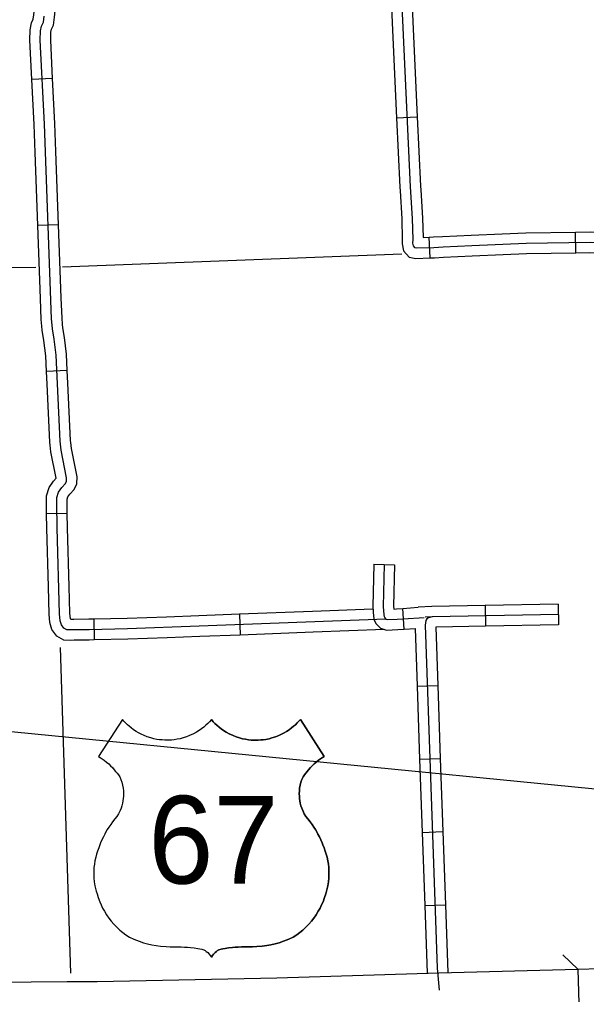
# Model space of a CAD drawing. Extents: x 1164457 to 1439835, y 1590918 to 1773502.
# Drawn here: x 1271432 to 1275531, y 1634109 to 1641151 of the extents above; entities that cross this region are included whole.
import ezdxf

# ---------------------------------------------------------------- set-up
doc = ezdxf.new("R2010")
doc.units = 0
for name, color, linetype in [('Level 15', 7, 'Continuous'), ('Level 22', 7, 'Continuous'), ('Level 32', 7, 'Continuous'), ('Level 37', 7, 'Continuous'), ('Level 45', 7, 'Continuous'), ('Level 49', 7, 'Continuous'), ('Level 5', 7, 'Continuous'), ('R_Draft', 7, 'Continuous')]:
    doc.layers.add(name, color=color, linetype=linetype)

msp = doc.modelspace()

# ---------------------------------------------------------------- linework, layer by layer
at = {"layer": 'Level 15'}
for points in [[(1264028.8, 1633877.9), (1264019.5, 1634127.7), (1266582.9, 1634223.2), (1269170.9, 1634189.2), (1269688.7, 1634190.8), (1270471.2, 1634190.8), (1271775.7, 1634202.7), (1271994.3, 1634202.4), (1273292.2, 1634228.7), (1274462.5, 1634266.1), (1275467.6, 1634293)], [(1275467.6, 1634293), (1275474.3, 1634043.1), (1274469.8, 1634016.2), (1273298.7, 1633978.7), (1271996.7, 1633952.4), (1271776.7, 1633952.7), (1270472.3, 1633940.8), (1269689.1, 1633940.8), (1269169.6, 1633939.2), (1266585.9, 1633973.1), (1264028.8, 1633877.9)], [(1275467.6, 1634293), (1275952.7, 1634306.1)]]:
    msp.add_lwpolyline(points, dxfattribs=at)
at = {"layer": 'Level 22'}
for points in [[(1272818.6, 1636094.4), (1272805.5, 1636079.6), (1272792.9, 1636066.7), (1272778.6, 1636053.3), (1272763.2, 1636040.1), (1272748.3, 1636028.5), (1272730.2, 1636015.9), (1272710.9, 1636003.8), (1272688.8, 1635991.7), (1272660.8, 1635978.7), (1272639.3, 1635970.3), (1272615, 1635962.5), (1272592.8, 1635956.7), (1272572.3, 1635952.5), (1272550.7, 1635949.1), (1272530.8, 1635947.1), (1272503.6, 1635945.8), (1272481.5, 1635946.1), (1272462.2, 1635947.3), (1272443.9, 1635949.2), (1272425.4, 1635952), (1272402, 1635956.7), (1272380.4, 1635962.4), (1272354.1, 1635971), (1272331.8, 1635979.7), (1272311.6, 1635989), (1272293, 1635998.7), (1272275.9, 1636008.8), (1272256.7, 1636021.4), (1272239.2, 1636034.3), (1272224.1, 1636046.6), (1272211.3, 1636057.9), (1272198.3, 1636070.5), (1272185.5, 1636084), (1272175.2, 1636095.8), (1272002.1, 1635828.1), (1272014.5, 1635820.8), (1272029.2, 1635811.1), (1272043.2, 1635801.2), (1272061.7, 1635786.8), (1272076.6, 1635774), (1272089.8, 1635761.7), (1272103.1, 1635748), (1272116.9, 1635732.8), (1272126.7, 1635720.9), (1272136.5, 1635708.4), (1272146.3, 1635694.6), (1272155.9, 1635680.1), (1272164.7, 1635663.1), (1272171.5, 1635642.3), (1272176.6, 1635621.6), (1272180.4, 1635599.5), (1272182.5, 1635579), (1272183.2, 1635559.1), (1272182.7, 1635540.6), (1272181.5, 1635525.7), (1272179, 1635507.5), (1272175.6, 1635490.3), (1272170.8, 1635471.8), (1272165.6, 1635455.5), (1272158.5, 1635437.2), (1272147.2, 1635413.6), (1272135.7, 1635395.1), (1272121.7, 1635378.4), (1272104.8, 1635356.6), (1272091.1, 1635337.6), (1272078.2, 1635318.5), (1272066.4, 1635299.8), (1272056.6, 1635283), (1272047.8, 1635267.3), (1272038.1, 1635248.6), (1272027.6, 1635226.8), (1272018.2, 1635205.4), (1272011.8, 1635189.5), (1272004.1, 1635169.2), (1271995.7, 1635144.2), (1271989, 1635123.5), (1271982.7, 1635100.9), (1271976.9, 1635074.6), (1271973, 1635051.2), (1271970.2, 1635026.8), (1271968.6, 1635000.2), (1271968.5, 1634975.2), (1271969.7, 1634950.7), (1271972.6, 1634922), (1271977.1, 1634894.8), (1271981.6, 1634874.2), (1271986.3, 1634856.1), (1271992.2, 1634835.7), (1272000.1, 1634810.3), (1272011.6, 1634779.5), (1272021.4, 1634756.8), (1272032.8, 1634733.4), (1272045.4, 1634710.5), (1272061.7, 1634684.2), (1272078.5, 1634660.1), (1272094.8, 1634639.1), (1272113.4, 1634617.5), (1272137.3, 1634592.7), (1272157.6, 1634573.9), (1272178.5, 1634556.4)], [(1272818.6, 1636094.4), (1272831.8, 1636079.6), (1272844.4, 1636066.7), (1272858.7, 1636053.3), (1272874.1, 1636040.1), (1272889, 1636028.5), (1272907.1, 1636015.9), (1272926.4, 1636003.8), (1272948.5, 1635991.7), (1272976.5, 1635978.7), (1272998, 1635970.3), (1273022.3, 1635962.5), (1273044.5, 1635956.7), (1273065, 1635952.5), (1273086.6, 1635949.1), (1273106.5, 1635947.1), (1273133.7, 1635945.8), (1273155.8, 1635946.1), (1273175.1, 1635947.3), (1273193.4, 1635949.2), (1273211.9, 1635952), (1273235.3, 1635956.7), (1273256.9, 1635962.4), (1273283.2, 1635971), (1273305.5, 1635979.7), (1273325.7, 1635989), (1273344.3, 1635998.7), (1273361.4, 1636008.8), (1273380.6, 1636021.4), (1273398.1, 1636034.3), (1273413.2, 1636046.6), (1273426, 1636057.9), (1273439, 1636070.5), (1273451.8, 1636084), (1273462.1, 1636095.8), (1273635.2, 1635828.1), (1273622.8, 1635820.8), (1273608.1, 1635811.1), (1273594.1, 1635801.2), (1273575.6, 1635786.8), (1273560.7, 1635774), (1273547.5, 1635761.7), (1273534.2, 1635748), (1273520.4, 1635732.8), (1273510.6, 1635720.9), (1273500.8, 1635708.4), (1273491, 1635694.6), (1273481.4, 1635680.1), (1273472.5, 1635663.1), (1273465.8, 1635642.3), (1273460.7, 1635621.6), (1273456.9, 1635599.5), (1273454.8, 1635579), (1273454.1, 1635559.1), (1273454.6, 1635540.6), (1273455.8, 1635525.7), (1273458.3, 1635507.5), (1273461.7, 1635490.3), (1273466.5, 1635471.8), (1273471.7, 1635455.5), (1273478.8, 1635437.2), (1273490.1, 1635413.6), (1273501.6, 1635395.1), (1273515.6, 1635378.4), (1273532.5, 1635356.6), (1273546.2, 1635337.6), (1273559.1, 1635318.5), (1273570.9, 1635299.8), (1273580.7, 1635283), (1273589.5, 1635267.3), (1273599.2, 1635248.6), (1273609.7, 1635226.8), (1273619.1, 1635205.4), (1273625.5, 1635189.5), (1273633.2, 1635169.2), (1273641.6, 1635144.2), (1273648.3, 1635123.5), (1273654.6, 1635100.9), (1273660.4, 1635074.6), (1273664.3, 1635051.2), (1273667.1, 1635026.8), (1273668.7, 1635000.2), (1273668.8, 1634975.2), (1273667.6, 1634950.7), (1273664.7, 1634922), (1273660.2, 1634894.8), (1273655.7, 1634874.2), (1273651, 1634856.1), (1273645.1, 1634835.7), (1273637.2, 1634810.3), (1273625.7, 1634779.5), (1273615.9, 1634756.8), (1273604.5, 1634733.4), (1273591.9, 1634710.5), (1273575.6, 1634684.2), (1273558.8, 1634660.1), (1273542.5, 1634639.1), (1273523.9, 1634617.5), (1273500, 1634592.7), (1273479.7, 1634573.9), (1273458.8, 1634556.4)], [(1272178.5, 1634556.4), (1272200.2, 1634540), (1272226.3, 1634522.9), (1272259.1, 1634508.3), (1272297.3, 1634493.6), (1272328.6, 1634483.4), (1272356.8, 1634475.6), (1272388.6, 1634468.2), (1272418.5, 1634462.8), (1272450.6, 1634458.3), (1272491.1, 1634454.8), (1272522, 1634453.8), (1272548.5, 1634453.9), (1272574.3, 1634453.6), (1272600.1, 1634452.8), (1272624.5, 1634451.6), (1272645.9, 1634450.2), (1272666.9, 1634448.4), (1272693.8, 1634445.6), (1272720, 1634442.3), (1272735.8, 1634440.1), (1272748.8, 1634437.6), (1272764.6, 1634431), (1272773.6, 1634426.1), (1272781.5, 1634420.8), (1272792.3, 1634412.1), (1272802.6, 1634401.7), (1272811, 1634390.9), (1272818.6, 1634378.4)], [(1273458.8, 1634556.4), (1273437.1, 1634540), (1273411, 1634522.9), (1273378.2, 1634508.3), (1273340, 1634493.6), (1273308.7, 1634483.4), (1273280.5, 1634475.6), (1273248.7, 1634468.2), (1273218.8, 1634462.8), (1273186.7, 1634458.3), (1273146.2, 1634454.8), (1273115.3, 1634453.8), (1273088.8, 1634453.9), (1273063, 1634453.6), (1273037.2, 1634452.8), (1273012.8, 1634451.6), (1272991.4, 1634450.2), (1272970.4, 1634448.4), (1272943.5, 1634445.6), (1272917.3, 1634442.3), (1272901.5, 1634440.1), (1272888.4, 1634437.6), (1272872.7, 1634431), (1272863.7, 1634426.1), (1272855.8, 1634420.8), (1272845, 1634412.1), (1272834.7, 1634401.7), (1272826.3, 1634390.9), (1272818.6, 1634378.4)]]:
    msp.add_lwpolyline(points, dxfattribs=at)
at = {"layer": 'Level 32'}
for p, q in [((1273992.7, 1637216.9), (1274142.7, 1637213.2)), ((1274798.4, 1636918.7), (1274801.3, 1636768.7)), ((1275326.3, 1636928.8), (1275329.2, 1636778.8)), ((1274213.3, 1636747.7), (1274202.5, 1636897.3)), ((1274305.4, 1636335.6), (1274455.4, 1636340.8)), ((1274323.8, 1635807.9), (1274473.7, 1635813.1)), ((1274342.2, 1635280.2), (1274492.1, 1635285.4)), ((1274360.6, 1634752.5), (1274510.5, 1634757.8))]:
    msp.add_line(p, q, dxfattribs=at)
for points in [[(1273992.7, 1637216.9), (1273985.1, 1636910.8), (1273990.2, 1636838.2), (1273996.3, 1636816.1), (1274006.9, 1636787.8), (1274040.8, 1636753.9), (1274085.3, 1636740.8), (1274166.5, 1636744.3), (1274213.3, 1636747.7)], [(1274067.7, 1637215.1), (1274060.1, 1636912.5), (1274064.4, 1636851), (1274067.7, 1636839.4), (1274071.5, 1636829.3), (1274080.3, 1636820.5), (1274094.5, 1636816.3), (1274162.2, 1636819.2), (1274319.7, 1636830.5), (1274356.9, 1636832.8)], [(1274142.7, 1637213.2), (1274135.2, 1636914.2), (1274136.7, 1636893.2), (1274157.9, 1636894.1), (1274202.5, 1636897.3)], [(1274798.4, 1636918.7), (1274412.5, 1636911.3), (1274314.8, 1636905.4)], [(1275326.3, 1636928.8), (1274798.4, 1636918.7)], [(1274202.5, 1636897.3), (1274314.8, 1636905.4)], [(1275327.8, 1636853.8), (1274415.4, 1636836.4), (1274364.8, 1636833.3)], [(1274415.4, 1636836.4), (1274389, 1636828.5), (1274377.1, 1636821.5), (1274368.3, 1636809.4), (1274365.1, 1636777.6), (1274451.4, 1634298.4), (1274466.2, 1634141.1)], [(1275329.2, 1636778.8), (1274801.3, 1636768.7)], [(1274213.3, 1636747.7), (1274290.9, 1636753.3)], [(1274290.9, 1636753.3), (1274305.4, 1636335.6)], [(1274801.3, 1636768.7), (1274440.7, 1636761.8)], [(1274440.7, 1636761.8), (1274455.4, 1636340.8)], [(1274305.4, 1636335.6), (1274323.8, 1635807.9)], [(1274455.4, 1636340.8), (1274473.7, 1635813.1)], [(1274323.8, 1635807.9), (1274342.2, 1635280.2)], [(1274473.7, 1635813.1), (1274492.1, 1635285.4)], [(1274342.2, 1635280.2), (1274360.6, 1634752.5)], [(1274492.1, 1635285.4), (1274510.5, 1634757.8)], [(1274360.6, 1634752.5), (1274377.6, 1634263.4)], [(1274510.5, 1634757.8), (1274527.5, 1634267.8)]]:
    msp.add_lwpolyline(points, dxfattribs=at)
at = {"layer": 'Level 37'}
msp.add_lwpolyline([(1275358.7, 1634396.2), (1275467.6, 1634293)], dxfattribs=at)
at = {"layer": 'Level 45'}
for p, q in [((1271671.2, 1640725), (1271521.4, 1640717.5)), ((1274157.6, 1640440.8), (1274307.4, 1640447.8)), ((1271714.3, 1639668.9), (1271564.4, 1639663.4)), ((1275453, 1639465.6), (1275450.9, 1639615.6)), ((1274399.4, 1639429.1), (1274393.9, 1639579)), ((1271776.9, 1638616.1), (1271627, 1638609.6)), ((1271777.4, 1637584.2), (1271627.5, 1637580.8)), ((1273022.2, 1636854.8), (1273028, 1636705)), ((1271967.9, 1636819.6), (1271971.4, 1636669.6))]:
    msp.add_line(p, q, dxfattribs=at)
for points in [[(1274257.5, 1641503.3), (1274259.8, 1641461.6), (1274282.6, 1640975.2)], [(1274108.7, 1641477.2), (1274110, 1641453.9), (1274132.8, 1640968.2)], [(1274184.9, 1641457.7), (1274256, 1639943.3), (1274270.2, 1639713.9), (1274274.1, 1639561.5), (1274272.8, 1639535.6), (1274276.7, 1639515.5), (1274287.7, 1639503.2), (1274301.3, 1639500.6), (1274427.5, 1639505.2), (1274493.8, 1639509.7), (1274700.9, 1639518.8), (1275094.8, 1639535.6), (1275558, 1639542.1), (1275620.2, 1639536.9), (1275665.5, 1639533), (1275970.1, 1639536.9), (1276329.8, 1639552.5), (1276476.5, 1639563.7), (1276571.4, 1639570), (1276664.7, 1639570.9), (1276917.4, 1639582.7)], [(1271521.4, 1640717.5), (1271507, 1641001.4), (1271509.8, 1641075.5), (1271518.6, 1641126.8), (1271531.5, 1641153.5), (1271535.3, 1641183.7), (1271540.1, 1641228.7), (1271542.8, 1641258.2), (1271545, 1641265.7)], [(1271671.2, 1640725), (1271657.1, 1641002.4), (1271659.3, 1641059.9), (1271662.9, 1641080.6), (1271677.3, 1641110.5), (1271684.3, 1641166.4), (1271689.4, 1641213.8)], [(1274080.3, 1636820.5), (1272731.5, 1636768.6), (1272211.4, 1636750.3), (1271934.1, 1636743.8), (1271825.3, 1636742.5), (1271799.9, 1636741.9), (1271773.4, 1636742.5), (1271752.1, 1636754.3), (1271734.8, 1636779.2), (1271726.1, 1636809), (1271721.6, 1636859.2), (1271704.7, 1637478.8), (1271700.8, 1637655.1), (1271702.1, 1637699.2), (1271713.8, 1637736.8), (1271737.1, 1637770.5), (1271763.1, 1637799), (1271770.8, 1637815.9), (1271772.1, 1637841.8), (1271733.2, 1638040.1), (1271725.5, 1638104.2), (1271706, 1638520.1), (1271697, 1638727.5), (1271682.7, 1638842.9), (1271671, 1638915.5), (1271669, 1638942.9), (1271664, 1638988.8), (1271612.7, 1640395.7), (1271582.1, 1641001.9), (1271584.6, 1641067.7), (1271590.8, 1641103.7), (1271604.4, 1641132), (1271609.8, 1641175.1)], [(1274132.8, 1640968.2), (1274157.6, 1640440.8)], [(1274282.6, 1640975.2), (1274307.4, 1640447.8)], [(1271695, 1640196.5), (1271687.7, 1640398.9), (1271671.2, 1640725)], [(1271545.1, 1640191.1), (1271537.8, 1640392.4), (1271521.4, 1640717.5)], [(1274157.6, 1640440.8), (1274181.1, 1639939.2), (1274182.8, 1639912.3)], [(1274307.4, 1640447.8), (1274330.9, 1639947.4), (1274332.5, 1639921.6)], [(1271564.4, 1639663.4), (1271545.1, 1640191.1)], [(1271714.3, 1639668.9), (1271695, 1640196.5)], [(1274182.8, 1639912.3), (1274195.3, 1639710.6), (1274199.1, 1639562.5), (1274197.5, 1639530.3), (1274207, 1639480.9), (1274248.8, 1639434.3), (1274295.6, 1639425.3), (1274399.4, 1639429.1)], [(1274332.5, 1639921.6), (1274345.2, 1639717.1), (1274348.7, 1639577.4), (1274393.9, 1639579)], [(1271583.6, 1639135.8), (1271564.4, 1639663.4)], [(1271733.5, 1639141.2), (1271714.3, 1639668.9)], [(1274393.9, 1639579), (1274423.6, 1639580.1), (1274489.6, 1639584.6), (1274697.6, 1639593.7), (1274920.9, 1639603.2)], [(1274920.9, 1639603.2), (1275092.7, 1639610.6), (1275450.9, 1639615.6)], [(1275450.9, 1639615.6), (1275560.6, 1639617.1), (1275626.5, 1639611.6), (1275668.3, 1639608.1), (1275968, 1639611.9), (1275976.2, 1639612.2)], [(1274399.4, 1639429.1), (1274431.4, 1639430.3), (1274497.9, 1639434.8), (1274704.1, 1639443.8), (1274927.3, 1639453.4)], [(1274927.3, 1639453.4), (1275097, 1639460.6), (1275453, 1639465.6)], [(1275453, 1639465.6), (1275555.4, 1639467), (1275613.9, 1639462.2), (1275662.8, 1639458), (1275972.2, 1639461.9), (1275982.7, 1639462.4)], [(1271627, 1638609.6), (1271622.2, 1638721.3), (1271608.4, 1638832.4), (1271596.5, 1638906.7), (1271594.3, 1638936), (1271589.1, 1638983.4), (1271583.6, 1639135.8)], [(1271776.9, 1638616.1), (1271771.8, 1638733.8), (1271757, 1638853.5), (1271745.6, 1638924.3), (1271743.7, 1638949.8), (1271738.9, 1638994.2), (1271733.5, 1639141.2)], [(1271653.3, 1638076.5), (1271650.7, 1638097.9), (1271631.1, 1638516.7), (1271627, 1638609.6)], [(1271802.2, 1638094.6), (1271800.3, 1638110.5), (1271781, 1638523.5), (1271776.9, 1638616.1)], [(1271627.5, 1637580.8), (1271625.8, 1637655.4), (1271627.5, 1637711.6), (1271645.6, 1637770), (1271678.3, 1637817.3), (1271696.6, 1637837.4), (1271659.1, 1638028.4), (1271653.3, 1638076.5)], [(1271777.4, 1637584.2), (1271775.9, 1637654.8), (1271776.8, 1637686.8), (1271782, 1637703.6), (1271796, 1637723.7), (1271826.3, 1637757.1), (1271845, 1637797.6), (1271847.5, 1637847.2), (1271807.4, 1638051.9), (1271802.2, 1638094.6)], [(1271641.3, 1637052.6), (1271629.8, 1637477), (1271627.5, 1637580.8)], [(1271791.2, 1637056.7), (1271779.7, 1637480.7), (1271777.4, 1637584.2)], [(1271971.4, 1636669.6), (1271935.4, 1636668.8), (1271826.5, 1636667.5), (1271800, 1636666.9), (1271753.2, 1636667.9), (1271700.6, 1636697.2), (1271666.2, 1636746.3), (1271652, 1636795), (1271646.7, 1636854.8), (1271641.3, 1637052.6)], [(1271967.9, 1636819.6), (1271932.8, 1636818.8), (1271824, 1636817.5), (1271801.9, 1636817), (1271800.1, 1636822.9), (1271796.5, 1636863.5), (1271791.2, 1637056.7)], [(1273022.2, 1636854.8), (1272728.8, 1636843.6), (1272494.8, 1636835.3)], [(1273549.8, 1636875.1), (1273022.2, 1636854.8)], [(1273986.4, 1636891.9), (1273549.8, 1636875.1)], [(1272494.8, 1636835.3), (1272209.2, 1636825.2), (1271967.9, 1636819.6)], [(1273555.6, 1636725.2), (1273028, 1636705)], [(1274070.9, 1636745), (1273555.6, 1636725.2)], [(1272500.1, 1636685.4), (1272213.6, 1636675.3), (1271971.4, 1636669.6)], [(1273028, 1636705), (1272734.3, 1636693.7), (1272500.1, 1636685.4)]]:
    msp.add_lwpolyline(points, dxfattribs=at)
at = {"layer": 'Level 49'}
for points in [[(1272818.6, 1636094.4), (1272805.5, 1636079.6), (1272792.9, 1636066.7), (1272778.6, 1636053.3), (1272763.2, 1636040.1), (1272748.3, 1636028.5), (1272730.2, 1636015.9), (1272710.9, 1636003.8), (1272688.8, 1635991.7), (1272660.8, 1635978.7), (1272639.3, 1635970.3), (1272615, 1635962.5), (1272592.8, 1635956.7), (1272572.3, 1635952.5), (1272550.7, 1635949.1), (1272530.8, 1635947.1), (1272503.6, 1635945.8), (1272481.5, 1635946.1), (1272462.2, 1635947.3), (1272443.9, 1635949.2), (1272425.4, 1635952), (1272402, 1635956.7), (1272380.4, 1635962.4), (1272354.1, 1635971), (1272331.8, 1635979.7), (1272311.6, 1635989), (1272293, 1635998.7), (1272275.9, 1636008.8), (1272256.7, 1636021.4), (1272239.2, 1636034.3), (1272224.1, 1636046.6), (1272211.3, 1636057.9), (1272198.3, 1636070.5), (1272185.5, 1636084), (1272175.2, 1636095.8), (1272002.1, 1635828.1), (1272014.5, 1635820.8), (1272029.2, 1635811.1), (1272043.2, 1635801.2), (1272061.7, 1635786.8), (1272076.6, 1635774), (1272089.8, 1635761.7), (1272103.1, 1635748), (1272116.9, 1635732.8), (1272126.7, 1635720.9), (1272136.5, 1635708.4), (1272146.3, 1635694.6), (1272155.9, 1635680.1), (1272164.7, 1635663.1), (1272171.5, 1635642.3), (1272176.6, 1635621.6), (1272180.4, 1635599.5), (1272182.5, 1635579), (1272183.2, 1635559.1), (1272182.7, 1635540.6), (1272181.5, 1635525.7), (1272179, 1635507.5), (1272175.6, 1635490.3), (1272170.8, 1635471.8), (1272165.6, 1635455.5), (1272158.5, 1635437.2), (1272147.2, 1635413.6), (1272135.7, 1635395.1), (1272121.7, 1635378.4), (1272104.8, 1635356.6), (1272091.1, 1635337.6), (1272078.2, 1635318.5), (1272066.4, 1635299.8), (1272056.6, 1635283), (1272047.8, 1635267.3), (1272038.1, 1635248.6), (1272027.6, 1635226.8), (1272018.2, 1635205.4), (1272011.8, 1635189.5), (1272004.1, 1635169.2), (1271995.7, 1635144.2), (1271989, 1635123.5), (1271982.7, 1635100.9), (1271976.9, 1635074.6), (1271973, 1635051.2), (1271970.2, 1635026.8), (1271968.6, 1635000.2), (1271968.5, 1634975.2), (1271969.7, 1634950.7), (1271972.6, 1634922), (1271977.1, 1634894.8), (1271981.6, 1634874.2), (1271986.3, 1634856.1), (1271992.2, 1634835.7), (1272000.1, 1634810.3), (1272011.6, 1634779.5), (1272021.4, 1634756.8), (1272032.8, 1634733.4), (1272045.4, 1634710.5), (1272061.7, 1634684.2), (1272078.5, 1634660.1), (1272094.8, 1634639.1), (1272113.4, 1634617.5), (1272137.3, 1634592.7), (1272157.6, 1634573.9), (1272178.5, 1634556.4)], [(1273458.8, 1634556.4), (1273479.7, 1634573.9), (1273500, 1634592.7), (1273523.9, 1634617.5), (1273542.5, 1634639.1), (1273558.8, 1634660.1), (1273575.6, 1634684.2), (1273591.9, 1634710.5), (1273604.5, 1634733.4), (1273615.9, 1634756.8), (1273625.7, 1634779.5), (1273637.2, 1634810.3), (1273645.1, 1634835.7), (1273651, 1634856.1), (1273655.7, 1634874.2), (1273660.2, 1634894.8), (1273664.7, 1634922), (1273667.6, 1634950.7), (1273668.8, 1634975.2), (1273668.7, 1635000.2), (1273667.1, 1635026.8), (1273664.3, 1635051.2), (1273660.4, 1635074.6), (1273654.6, 1635100.9), (1273648.3, 1635123.5), (1273641.6, 1635144.2), (1273633.2, 1635169.2), (1273625.5, 1635189.5), (1273619.1, 1635205.4), (1273609.7, 1635226.8), (1273599.2, 1635248.6), (1273589.5, 1635267.3), (1273580.7, 1635283), (1273570.9, 1635299.8), (1273559.1, 1635318.5), (1273546.2, 1635337.6), (1273532.5, 1635356.6), (1273515.6, 1635378.4), (1273501.6, 1635395.1), (1273490.1, 1635413.6), (1273478.8, 1635437.2), (1273471.7, 1635455.5), (1273466.5, 1635471.8), (1273461.7, 1635490.3), (1273458.3, 1635507.5), (1273455.8, 1635525.7), (1273454.6, 1635540.6), (1273454.1, 1635559.1), (1273454.8, 1635579), (1273456.9, 1635599.5), (1273460.7, 1635621.6), (1273465.8, 1635642.3), (1273472.5, 1635663.1), (1273481.4, 1635680.1), (1273491, 1635694.6), (1273500.8, 1635708.4), (1273510.6, 1635720.9), (1273520.4, 1635732.8), (1273534.2, 1635748), (1273547.5, 1635761.7), (1273560.7, 1635774), (1273575.6, 1635786.8), (1273594.1, 1635801.2), (1273608.1, 1635811.1), (1273622.8, 1635820.8), (1273635.2, 1635828.1), (1273462.1, 1636095.8), (1273451.8, 1636084), (1273439, 1636070.5), (1273426, 1636057.9), (1273413.2, 1636046.6), (1273398.1, 1636034.3), (1273380.6, 1636021.4), (1273361.4, 1636008.8), (1273344.3, 1635998.7), (1273325.7, 1635989), (1273305.5, 1635979.7), (1273283.2, 1635971), (1273256.9, 1635962.4), (1273235.3, 1635956.7), (1273211.9, 1635952), (1273193.4, 1635949.2), (1273175.1, 1635947.3), (1273155.8, 1635946.1), (1273133.7, 1635945.8), (1273106.5, 1635947.1), (1273086.6, 1635949.1), (1273065, 1635952.5), (1273044.5, 1635956.7), (1273022.3, 1635962.5), (1272998, 1635970.3), (1272976.5, 1635978.7), (1272948.5, 1635991.7), (1272926.4, 1636003.8), (1272907.1, 1636015.9), (1272889, 1636028.5), (1272874.1, 1636040.1), (1272858.7, 1636053.3), (1272844.4, 1636066.7), (1272831.8, 1636079.6), (1272818.6, 1636094.4)], [(1272178.5, 1634556.4), (1272200.2, 1634540), (1272226.3, 1634522.9), (1272259.1, 1634508.3), (1272297.3, 1634493.6), (1272328.6, 1634483.4), (1272356.8, 1634475.6), (1272388.6, 1634468.2), (1272418.5, 1634462.8), (1272450.6, 1634458.3), (1272491.1, 1634454.8), (1272522, 1634453.8), (1272548.5, 1634453.9), (1272574.3, 1634453.6), (1272600.1, 1634452.8), (1272624.5, 1634451.6), (1272645.9, 1634450.2), (1272666.9, 1634448.4), (1272693.8, 1634445.6), (1272720, 1634442.3), (1272735.8, 1634440.1), (1272748.8, 1634437.6), (1272764.6, 1634431), (1272773.6, 1634426.1), (1272781.5, 1634420.8), (1272792.3, 1634412.1), (1272802.6, 1634401.7), (1272811, 1634390.9), (1272818.6, 1634378.4)], [(1272818.6, 1634378.4), (1272826.3, 1634390.9), (1272834.7, 1634401.7), (1272845, 1634412.1), (1272855.8, 1634420.8), (1272863.7, 1634426.1), (1272872.7, 1634431), (1272888.4, 1634437.6), (1272901.5, 1634440.1), (1272917.3, 1634442.3), (1272943.5, 1634445.6), (1272970.4, 1634448.4), (1272991.4, 1634450.2), (1273012.8, 1634451.6), (1273037.2, 1634452.8), (1273063, 1634453.6), (1273088.8, 1634453.9), (1273115.3, 1634453.8), (1273146.2, 1634454.8), (1273186.7, 1634458.3), (1273218.8, 1634462.8), (1273248.7, 1634468.2), (1273280.5, 1634475.6), (1273308.7, 1634483.4), (1273340, 1634493.6), (1273378.2, 1634508.3), (1273411, 1634522.9), (1273437.1, 1634540), (1273458.8, 1634556.4)]]:
    msp.add_lwpolyline(points, dxfattribs=at)
at = {"layer": 'Level 5'}
for points in [[(1271741.8, 1639365.5), (1274196.6, 1639458.3)], [(1266581.1, 1639322), (1271548.6, 1639361.1)], [(1271725.8, 1636615.4), (1271800.3, 1634264.4)]]:
    msp.add_lwpolyline(points, dxfattribs=at)
at = {"layer": 'R_Draft'}
msp.add_line((1283713.8, 1634794.1), (1223029.8, 1640753.2), dxfattribs=at)

# ---------------------------------------------------------------- texts
at = {"layer": 'Level 22'}
msp.add_text('67', height=633.6, dxfattribs=at).set_placement((1272362.3, 1634910.3))

doc.saveas('drawing.dxf')
